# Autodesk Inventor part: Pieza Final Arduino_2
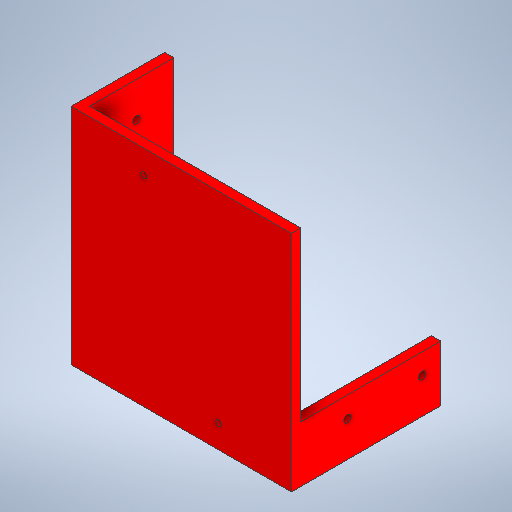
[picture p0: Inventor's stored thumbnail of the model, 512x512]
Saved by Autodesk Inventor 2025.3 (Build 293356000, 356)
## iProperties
Created: 2025-11
Part Number: Pieza Final Arduino_2
Material: Genérico
Document SubType Name: Modeling
Designer: Dell
Density: 1 g/cm^3
Appearance: Valor por defecto
Author: Dell
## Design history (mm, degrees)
sketch "Boceto1"
  geometry: L1 (-118, 0)-(118, 0); L2 (118, 0)-(118, 240); L3 (118, 240)-(-118, 240); L4 (-118, 240)-(-118, 0); 1 further point
  constraints: 8 end point, 2 perpendicular, 1 horizontal, 1 midpoint, 1 vertical
  dimensions: "d0" = 236 distance of L1.start L1.end; "d1" = 240 distance of L1.end L2.end
extrude "Extrusión1" new body sketch "Boceto1" distance "d2" = 10; taper "d3" = 0 deg
sketch "Boceto2"
  geometry: L1 (-118, 0)-(118, 0) reference; L2 (-118, 240)-(-118, 0) reference; L3 (118, 240)-(-118, 240) reference; L4 (-118, 240)-(-103, 240); L5 (118, 240)-(103, 240); L6 (118, 0)-(103, 0); L7 (103, 10)-(-103, 10); L8 (118, 0)-(118, 240) reference; L9 (103, 10)-(103, 180); L10 (-103, 10)-(-103, 180); L11 (-118, 240)-(-103, 240); L12 (-103, 230)-(-103, 180); L13 (-103, 230)-(103, 230); L14 (103, 230)-(103, 180); 1 further point
  constraints: 20 end point, 3 point on line, 2 horizontal, 1 collinear, 1 parallel
extrude "Extrusión2" join sketch "Boceto2" distance "d11" = 80; taper "d12" = 0 deg
sketch "Boceto3"
  geometry: L1 (118, 240)-(118, 0) reference; L2 (118, 0)-(108, 0); L3 (118, 0)-(-118, 0) reference; L4 (108, 0)-(108, 240); L5 (-118, 240)-(118, 240) reference; L6 (118, 240)-(118, 0); L7 (-118, 0)-(-118, 240) reference; L8 (-118, 220)-(-118, 240); L9 (-103, 240)-(-118, 240); L10 (-118, 0)-(-108.5, 0); L11 (-103, 230)-(-103, 10) reference; L12 (-118, 0)-(-113.25, 0); L13 (-118, 40)-(-118, 0); L14 (-118, 0)-(-113.25, 0); L15 (-108, 40)-(-108, 0); L16 (-118, 0)-(-108, 0); L17 (-118, 0)-(-118, 40); L18 (-108, 40)-(-108, 60); L19 (-108, 60)-(-118, 60); L20 (-118, 40)-(-118, 60); 3 further points
  constraints: 30 end point, 9 point on line, 6 collinear, 3 perpendicular, 1 midpoint, 1 parallel, 1 vertical
  dimensions: "d13" = 10 distance of L1.end L2.end; "d94" = 60 distance of L15.end L18.end
extrude "Extrusión5" join sketch "Boceto3" distance "d21" = 90; taper "d22" = 0 deg
extrude "Extrusión6" join sketch "Boceto3" distance "d23" = 150; taper "d24" = 0 deg
sketch "Boceto4"
  geometry: L1 (40, 37.5)-(50, 37.5); C1 r 4 at (50, 37.5); C2 r 4 at (50, 202.5); 4 further points; 1 other entity
  constraints: 2 centre point, 2 end point, 1 coincident, 1 horizontal, 1 other
extrude "Extrusión7" cut sketch "Boceto4" distance "d29" = 10; taper "d30" = 0 deg
sketch "Boceto5"
  geometry: L1 (0, 0)-(0, 240) reference; L2 (0, 20)-(50, 20); L3 (0, 60)-(-150, 60) reference; L4 (0, 60)-(-150, 60) reference; C1 r 4 at (-50, 38); C2 r 4 at (-130, 38)
  constraints: 2 centre point, 2 end point, 1 horizontal, 1 point on line
  dimensions: "d51" = 8 diameter of C1
extrude "Extrusión8" cut sketch "Boceto5" distance "d44" = 10; taper "d45" = 0 deg
sketch "Boceto7"
  geometry: L1 (-90, 240)-(0, 240) reference; L2 (-180, 0)-(0, 0) reference; L3 (0, 240)-(-80, 240); L4 (-80, 240)-(-80, 0); L5 (-80, 0)-(0, 0); L6 (0, 0)-(0, 240); 3 further points
  constraints: 8 end point, 2 parallel, 1 horizontal, 1 perpendicular, 1 point on line
  dimensions: "d53" = 80 distance of L5.end L4.end
extrude "Extrusión9" cut sketch "Boceto7" extent not by distance; stored distance "d54" = 0; taper "d55" = 0 deg
sketch "Boceto9"
  geometry: L1 (-118, 0)-(-118, 240) reference; L2 (118, 60)-(118, 240) reference; L3 (-55, 230)-(55, 230); L4 (55, 230)-(55, 10); L5 (55, 10)-(-55, 10); L6 (-55, 10)-(-55, 230); L7 (-55, 230)-(55, 10); L8 (55, 230)-(-55, 10); L9 (-55, 230)-(-40, 230); L10 (55, 10)-(40, 10); C1 r 3.1 at (-40, 215); C2 r 3.1 at (40, 25); 2 further points
  constraints: 16 end point, 2 centre point, 2 midpoint, 2 parallel, 2 point on line, 1 horizontal, 1 perpendicular
  dimensions: "d84" = 110 distance of L4.end L5.end; "d85" = 220 distance of L3.end L4.end; "d88" = 6.2 diameter of C1
extrude "Extrusión10" cut sketch "Boceto9" distance "d92" = 10; taper "d93" = 0 deg
node "Sólido1"
